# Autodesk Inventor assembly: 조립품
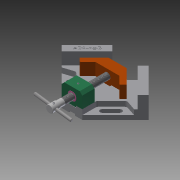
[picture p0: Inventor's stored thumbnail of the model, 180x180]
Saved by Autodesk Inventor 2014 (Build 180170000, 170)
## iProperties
Created: 2019-04
Part Number: 조립품
Document SubType Name: Assembly
Designer: kh
Author: kh
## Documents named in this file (11)
- C:\Users\kh\Desktop\490407V1012\조립품.iam
- C:\Users\kh\Desktop\490407V1012\베이스.ipt
- C:\Users\kh\Desktop\490407V1012\리드스크류.ipt
- C:\Users\kh\Desktop\490407V1012\멈춤나사 M4x5.ipt
- C:\Users\kh\Desktop\490407V1012\멈춤나사 M4x10.ipt
- C:\Users\kh\Desktop\490407V1012\볼트 M4x16.ipt
- C:\Users\kh\Desktop\490407V1012\부시.ipt
- C:\Users\kh\Desktop\490407V1012\서포트.ipt
- C:\Users\kh\Desktop\490407V1012\조.ipt
- C:\Users\kh\Desktop\490407V1012\평행 핀 2.5x24.ipt
- C:\Users\kh\Desktop\490407V1012\핸들.ipt
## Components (1 placed, 1 different names)
1. 핸들:1 — Mate:9, Mate:10, Mate:12, Mate:13, Mate:14
## Component patterns: Component Pattern 1:2 (2 elements)
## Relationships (5: Mate 5)
- Mate:9: 핸들:1
- Mate:10: 핸들:1
- Mate:12: 핸들:1
- Mate:13: 핸들:1
- Mate:14: 핸들:1
